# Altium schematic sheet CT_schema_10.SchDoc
size 147 x 119 mm
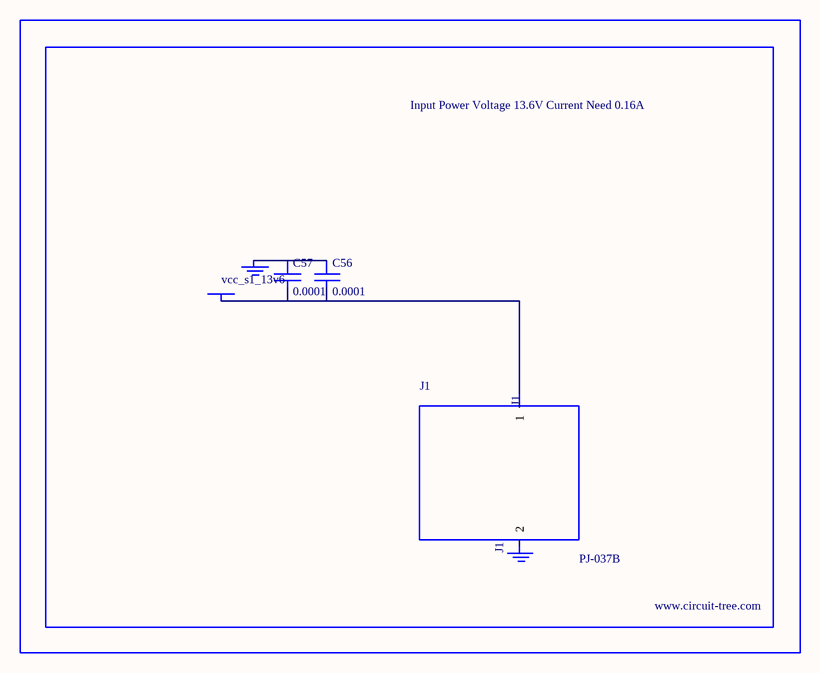
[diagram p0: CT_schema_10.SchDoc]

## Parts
BORDER9  (no value)
C56  0.0001  [EXV-9H]
C57  0.0001  [EXV-9H]
GND_INSTANCE_9_0  (no value)
GND_INSTANCE_9_1  (no value)
J1  PJ-037B  [PJ-037B_PACKAGE]
POWER_INSTANCE_9_0  vcc_s1_13v6

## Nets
NetC56_1: C56.1 C57.1 GND_INSTANCE_9_0.0(GND)
NetC56_2: C56.2 C57.2 J1.1 POWER_INSTANCE_9_0.0(PWR)

Not connected (* = marked no-connect by the designer): GND_INSTANCE_9_1 0(GND); J1 2

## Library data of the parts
BORDER9 = BORDER_PAGE9
C56 C57 = EDK107M035A9HAA
GND_INSTANCE_9_0 GND_INSTANCE_9_1 = GND
POWER_INSTANCE_9_0 = PWR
